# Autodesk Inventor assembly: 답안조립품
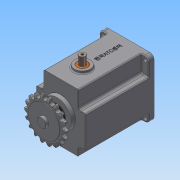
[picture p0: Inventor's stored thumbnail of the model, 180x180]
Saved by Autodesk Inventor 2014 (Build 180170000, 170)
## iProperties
Created: 2016-05
Part Number: 답안조립품
Document SubType Name: Assembly
Designer: 703-04
Author: 703-04
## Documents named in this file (16)
- C:\Users\703-04\Desktop\360508V1007\답안조립품.iam
- C:\Users\703-04\Desktop\360508V1007\본체.ipt
- C:\Users\703-04\Desktop\360508V1007\메인축.ipt
- C:\Users\703-04\Desktop\360508V1007\베어링 608.ipt
- C:\Users\703-04\Desktop\360508V1007\베어링 6003.ipt
- C:\Users\703-04\Desktop\360508V1007\키 5 x 5 x 18.ipt
- C:\Users\703-04\Desktop\360508V1007\오일실 8 22 7.ipt
- C:\Users\703-04\Desktop\360508V1007\오일실 17 32 8.ipt
- C:\Users\703-04\Desktop\360508V1007\서브축.ipt
- C:\Users\703-04\Desktop\360508V1007\커버.ipt
- C:\Users\703-04\Desktop\360508V1007\가변 스프링.ipt
- C:\Users\703-04\Desktop\360508V1007\멈춤나사 M3x8.ipt
- C:\Users\703-04\Desktop\360508V1007\부시.ipt
- C:\Users\703-04\Desktop\360508V1007\스프로킷.ipt
- C:\Users\703-04\Desktop\360508V1007\슬라이더.ipt
- C:\Users\703-04\Desktop\360508V1007\볼트 M4 x 10.ipt
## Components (3 placed, 2 different names)
1. 가변 스프링:1
2. ISO 4762 M4 x 10:1
3. ISO 4762 M4 x 10:2
